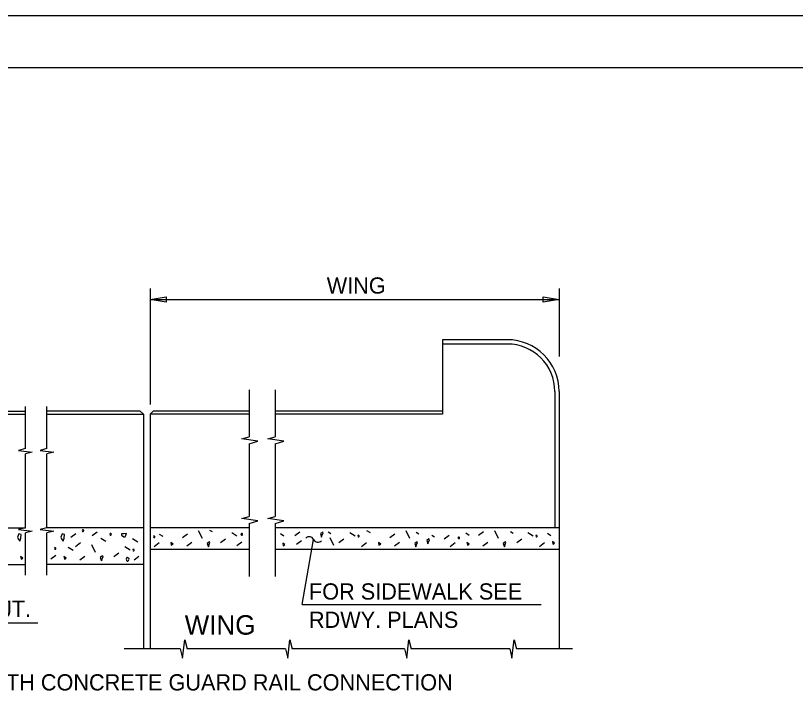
# Model space of a CAD drawing. Extents: x 0 to 68, y 0 to 47.1.
# Drawn here: x 27.23 to 42.27, y 30.88 to 44 of the extents above; entities that cross this region are included whole.
import ezdxf

# ---------------------------------------------------------------- set-up
doc = ezdxf.new("R2010")
doc.units = 0
for name, color, linetype in [('BORDER_ANNO_Cutsheet', 7, 'Continuous'), ('BRDG_ANNO_Anno-Sheet', 7, 'Continuous'), ('BRDG_ANNO_General-Notes', 7, 'Continuous'), ('BRDG_BASE_Obj-Line', 7, 'Continuous'), ('BRDG_BASE_Pattern', 7, 'Continuous')]:
    doc.layers.add(name, color=color, linetype=linetype)

msp = doc.modelspace()

# ---------------------------------------------------------------- linework, layer by layer
at = {"layer": 'BORDER_ANNO_Cutsheet'}
msp.add_lwpolyline([(0, 44), (68, 44), (68, 0), (0, 0)], close=True, dxfattribs=at)
at = {"layer": 'BRDG_ANNO_Anno-Sheet'}
msp.add_lwpolyline([(3, 43), (67, 43), (67, 1), (3, 1)], close=True, dxfattribs=at)
at = {"layer": 'BRDG_ANNO_General-Notes'}
for p, q in [((29.826, 38.74), (29.826, 36.508)), ((37.712, 38.741), (37.712, 37.435)), ((29.826, 38.532), (30.136, 38.584)), ((29.826, 38.532), (37.712, 38.532)), ((30.136, 38.481), (29.826, 38.532)), ((30.136, 38.584), (30.136, 38.481)), ((37.402, 38.481), (37.402, 38.584)), ((37.402, 38.584), (37.712, 38.532)), ((37.712, 38.532), (37.402, 38.481)), ((32.759, 32.652), (32.979, 33.908)), ((32.759, 32.652), (37.364, 32.652)), ((27.666, 32.295), (25.024, 32.295))]:
    msp.add_line(p, q, dxfattribs=at)
for centre, start, end in [((32.893, 33.864), 26.9511, 133.2114), ((33.065, 33.952), 206.9511, 313.2113)]:
    msp.add_arc(centre, 0.0969, start, end, dxfattribs=at)
at = {"layer": 'BRDG_BASE_Obj-Line'}
for p, q in [((35.462, 37.756), (35.462, 36.319)), ((36.712, 37.756), (35.462, 37.756)), ((36.712, 37.673), (35.462, 37.673)), ((31.74, 36.792), (31.74, 35.885)), ((32.24, 36.792), (32.24, 35.885)), ((37.629, 36.756), (37.629, 34.131)), ((37.712, 36.756), (37.712, 36.381)), ((25.906, 36.382), (27.423, 36.382)), ((27.423, 35.657), (27.423, 36.469)), ((27.839, 35.657), (27.839, 36.469)), ((29.638, 36.382), (27.839, 36.382)), ((29.638, 36.382), (29.701, 36.319)), ((29.826, 36.319), (29.888, 36.382)), ((31.74, 36.382), (29.888, 36.382)), ((35.462, 36.381), (32.24, 36.381)), ((37.712, 36.381), (37.712, 34.131)), ((25.99, 36.319), (27.423, 36.319)), ((27.839, 36.319), (29.701, 36.319)), ((29.701, 36.319), (29.701, 31.798)), ((29.826, 36.319), (29.826, 31.798)), ((31.74, 36.319), (29.826, 36.319)), ((35.462, 36.319), (32.24, 36.319)), ((31.595, 35.843), (31.74, 35.885)), ((31.903, 35.803), (31.595, 35.843)), ((31.74, 35.751), (31.903, 35.803)), ((32.095, 35.843), (32.24, 35.885)), ((32.403, 35.803), (32.095, 35.843)), ((32.24, 35.751), (32.403, 35.803)), ((27.423, 35.657), (27.29, 35.624)), ((27.839, 35.657), (27.707, 35.624)), ((31.74, 35.751), (31.74, 34.35)), ((32.24, 35.751), (32.24, 34.35)), ((27.29, 35.624), (27.555, 35.591)), ((27.555, 35.591), (27.423, 35.557)), ((27.423, 34.131), (27.423, 35.557)), ((27.707, 35.624), (27.972, 35.591)), ((27.972, 35.591), (27.839, 35.557)), ((27.839, 34.131), (27.839, 35.557)), ((31.595, 34.308), (31.74, 34.35)), ((31.903, 34.267), (31.595, 34.308)), ((32.095, 34.308), (32.24, 34.35)), ((32.403, 34.267), (32.095, 34.308)), ((23.572, 34.131), (27.423, 34.131)), ((27.423, 34.131), (27.29, 34.098)), ((27.839, 34.131), (27.707, 34.098)), ((29.701, 34.131), (27.839, 34.131)), ((31.74, 34.132), (29.826, 34.132)), ((31.74, 34.215), (31.903, 34.267)), ((31.74, 34.215), (31.74, 33.192)), ((32.24, 34.215), (32.403, 34.267)), ((32.24, 34.215), (32.24, 33.192)), ((37.712, 34.131), (32.24, 34.131)), ((37.712, 34.131), (37.712, 31.798)), ((27.29, 34.098), (27.555, 34.065)), ((27.555, 34.065), (27.423, 34.032)), ((27.423, 33.219), (27.423, 34.032)), ((27.707, 34.098), (27.972, 34.065)), ((27.972, 34.065), (27.839, 34.032)), ((27.839, 33.219), (27.839, 34.032)), ((31.74, 33.715), (29.826, 33.715)), ((37.712, 33.715), (32.24, 33.715)), ((23.572, 33.423), (27.423, 33.423)), ((29.701, 33.423), (27.839, 33.423)), ((30.451, 31.622), (30.495, 31.974)), ((30.495, 31.974), (30.539, 31.798)), ((32.48, 31.622), (32.524, 31.974)), ((32.524, 31.974), (32.568, 31.798)), ((34.774, 31.622), (34.818, 31.974)), ((34.818, 31.974), (34.862, 31.798)), ((36.803, 31.622), (36.847, 31.974)), ((36.847, 31.974), (36.892, 31.798)), ((30.407, 31.798), (29.326, 31.798)), ((30.407, 31.798), (30.451, 31.622)), ((32.436, 31.798), (30.539, 31.798)), ((32.436, 31.798), (32.48, 31.622)), ((33.649, 31.798), (32.568, 31.798)), ((34.73, 31.798), (33.649, 31.798)), ((34.73, 31.798), (34.774, 31.622)), ((36.759, 31.798), (34.862, 31.798)), ((36.759, 31.798), (36.803, 31.622)), ((37.972, 31.798), (36.892, 31.798))]:
    msp.add_line(p, q, dxfattribs=at)
for radius in [1, 0.917]:
    msp.add_arc((36.712, 36.756), radius, 0, 90, dxfattribs=at)
at = {"layer": 'BRDG_BASE_Pattern'}
for p, q in [((28.396, 34.015), (28.299, 33.942)), ((28.807, 34.05), (28.711, 33.977)), ((30.005, 34.012), (30.073, 33.969)), ((30.546, 34.012), (30.45, 33.939)), ((30.755, 34.081), (30.829, 33.934)), ((30.97, 34.089), (31.021, 34.058)), ((31.403, 34.042), (31.502, 33.98)), ((32.339, 34.019), (32.406, 33.976)), ((32.712, 34.047), (32.615, 33.974)), ((33.261, 34.054), (33.312, 34.022)), ((33.68, 34.042), (33.779, 33.979)), ((33.999, 34.082), (34.067, 34.039)), ((34.548, 34.012), (34.451, 33.939)), ((34.756, 34.081), (34.83, 33.934)), ((34.957, 34.047), (35.008, 34.015)), ((35.259, 33.989), (35.31, 33.957)), ((35.594, 33.984), (35.498, 33.911)), ((35.911, 34.033), (35.979, 33.99)), ((36.255, 34.054), (36.159, 33.981)), ((36.464, 34.081), (36.538, 33.934)), ((36.778, 34.061), (36.828, 34.029)), ((37.112, 34.042), (37.211, 33.979)), ((37.487, 34.026), (37.555, 33.983)), ((28.487, 33.842), (28.39, 33.768)), ((28.876, 33.935), (28.975, 33.872)), ((29.49, 33.924), (29.589, 33.862)), ((30, 33.84), (29.903, 33.767)), ((30.631, 33.85), (30.535, 33.777)), ((31.282, 33.916), (31.186, 33.843)), ((31.594, 33.857), (31.498, 33.784)), ((32.745, 33.884), (32.649, 33.811)), ((33.291, 33.943), (33.364, 33.796)), ((33.559, 33.915), (33.463, 33.842)), ((34.001, 33.84), (33.905, 33.767)), ((34.633, 33.85), (34.536, 33.776)), ((35.709, 33.84), (35.612, 33.767)), ((36.34, 33.85), (36.244, 33.776)), ((36.991, 33.915), (36.895, 33.842)), ((37.433, 33.84), (37.336, 33.767)), ((28.245, 33.761), (28.344, 33.698)), ((28.695, 33.812), (28.769, 33.664)), ((29.343, 33.773), (29.442, 33.71)), ((28.011, 33.601), (27.915, 33.528)), ((28.572, 33.58), (28.475, 33.507)), ((29.222, 33.646), (29.126, 33.573)), ((29.613, 33.581), (29.517, 33.508))]:
    msp.add_line(p, q, dxfattribs=at)
for points in [[(27.296, 34.018), (27.274, 33.952), (27.285, 33.918), (27.318, 33.874), (27.333, 33.933), (27.344, 34)], [(28.132, 34.018), (28.109, 33.952), (28.121, 33.918), (28.154, 33.874), (28.169, 33.933), (28.18, 34)], [(28.519, 34.078), (28.525, 34.06), (28.531, 34.06), (28.538, 34.062), (28.543, 34.067), (28.549, 34.078), (28.547, 34.089), (28.538, 34.091), (28.534, 34.095), (28.527, 34.095)], [(29.051, 34.007), (29.056, 33.989), (29.062, 33.989), (29.069, 33.99), (29.075, 33.996), (29.08, 34.007), (29.078, 34.018), (29.069, 34.02), (29.065, 34.024), (29.058, 34.024)], [(29.319, 34.018), (29.274, 34.014), (29.274, 33.992), (29.322, 33.959), (29.348, 33.955), (29.374, 34.025)], [(29.901, 33.976), (29.891, 33.956), (29.902, 33.944), (29.916, 33.944), (29.921, 33.95), (29.921, 33.961), (29.919, 33.966), (29.913, 33.972)], [(31.587, 34.024), (31.578, 34.004), (31.589, 33.993), (31.602, 33.993), (31.607, 33.999), (31.607, 34.01), (31.606, 34.015), (31.6, 34.021)], [(33.11, 34.021), (33.132, 33.954), (33.132, 33.962), (33.162, 34.036), (33.154, 34.05)], [(33.838, 33.989), (33.829, 33.969), (33.84, 33.958), (33.853, 33.958), (33.859, 33.964), (33.859, 33.975), (33.857, 33.98), (33.851, 33.986)], [(37.27, 33.989), (37.261, 33.969), (37.272, 33.958), (37.285, 33.958), (37.291, 33.964), (37.291, 33.975), (37.289, 33.98), (37.283, 33.986)], [(30.226, 33.848), (30.234, 33.796), (30.271, 33.818)], [(30.927, 33.832), (30.95, 33.765), (30.95, 33.772), (30.979, 33.846), (30.972, 33.861)], [(32.383, 33.839), (32.39, 33.787), (32.427, 33.809)], [(34.227, 33.847), (34.235, 33.796), (34.272, 33.818)], [(34.928, 33.831), (34.951, 33.765), (34.951, 33.772), (34.981, 33.846), (34.973, 33.861)], [(35.159, 33.889), (35.181, 33.822), (35.181, 33.829), (35.211, 33.903), (35.203, 33.918)], [(35.772, 33.954), (35.762, 33.934), (35.773, 33.923), (35.786, 33.923), (35.792, 33.929), (35.792, 33.939), (35.79, 33.945), (35.784, 33.951)], [(35.935, 33.847), (35.943, 33.796), (35.98, 33.818)], [(36.636, 33.831), (36.659, 33.765), (36.659, 33.772), (36.688, 33.846), (36.681, 33.861)], [(37.582, 33.868), (37.589, 33.817), (37.626, 33.839)], [(27.992, 33.751), (27.982, 33.731), (27.993, 33.719), (28.007, 33.719), (28.012, 33.725), (28.012, 33.736), (28.01, 33.741), (28.004, 33.747)], [(29.502, 33.72), (29.492, 33.7), (29.503, 33.689), (29.516, 33.689), (29.522, 33.695), (29.522, 33.705), (29.52, 33.711), (29.514, 33.717)], [(27.331, 33.578), (27.339, 33.526), (27.376, 33.549)], [(28.167, 33.578), (28.174, 33.526), (28.211, 33.549)], [(28.867, 33.562), (28.89, 33.495), (28.89, 33.503), (28.92, 33.577), (28.912, 33.591)]]:
    msp.add_lwpolyline(points, close=True, dxfattribs=at)
for points in [[(29.386, 33.488), (29.401, 33.491), (29.412, 33.502), (29.423, 33.525), (29.42, 33.546), (29.401, 33.55), (29.394, 33.558), (29.379, 33.558), (29.364, 33.525)], [(29.364, 33.525), (29.376, 33.488)]]:
    msp.add_lwpolyline(points, dxfattribs=at)

# ---------------------------------------------------------------- texts
at = {"layer": 'BRDG_ANNO_General-Notes'}
for s, height, p in [('WING', 0.3125, (33.232, 38.644)), ('FOR SIDEWALK SEE  ', 0.3125, (32.89, 32.749)), ('CONST. JT.', 0.3125, (25.258, 32.415)), ('RDWY. PLANS', 0.3125, (32.889, 32.204)), ('WING', 0.375, (30.494, 32.073)), ('WITH CONCRETE GUARD RAIL CONNECTION', 0.3125, (26.537, 30.998))]:
    msp.add_text(s, height=height, dxfattribs=at).set_placement(p)

doc.saveas('drawing.dxf')
